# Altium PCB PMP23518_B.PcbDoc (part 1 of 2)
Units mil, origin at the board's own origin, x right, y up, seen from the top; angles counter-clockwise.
Board outline 2200 x 2200 mil, 2 copper layers (Top Layer, Bottom Layer), stack 62 mil thick; 74 components, 34 nets, 163 pads, 51 vias.
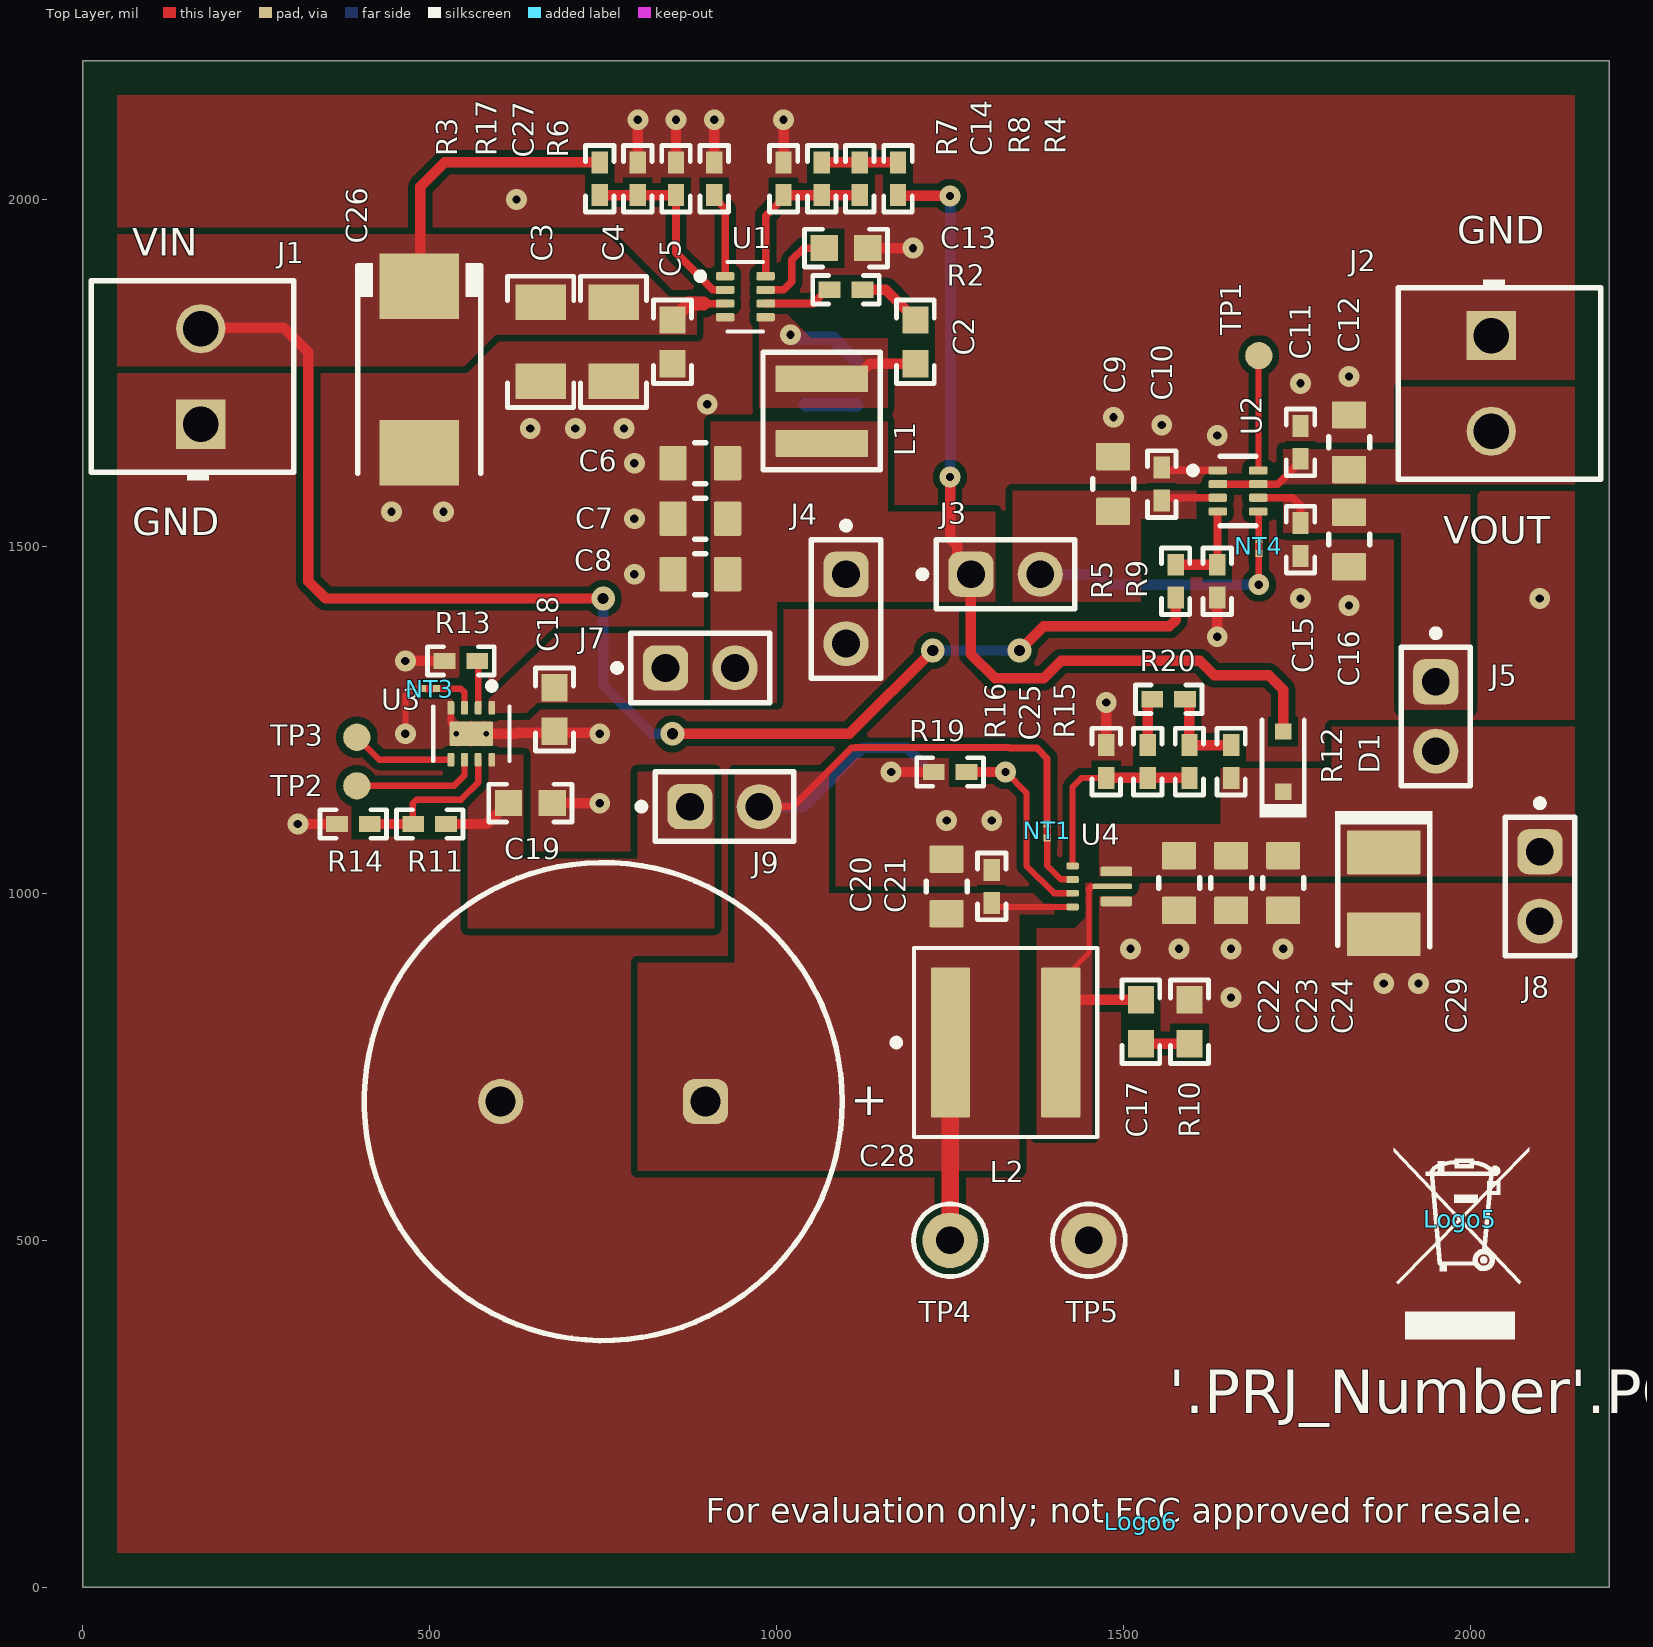
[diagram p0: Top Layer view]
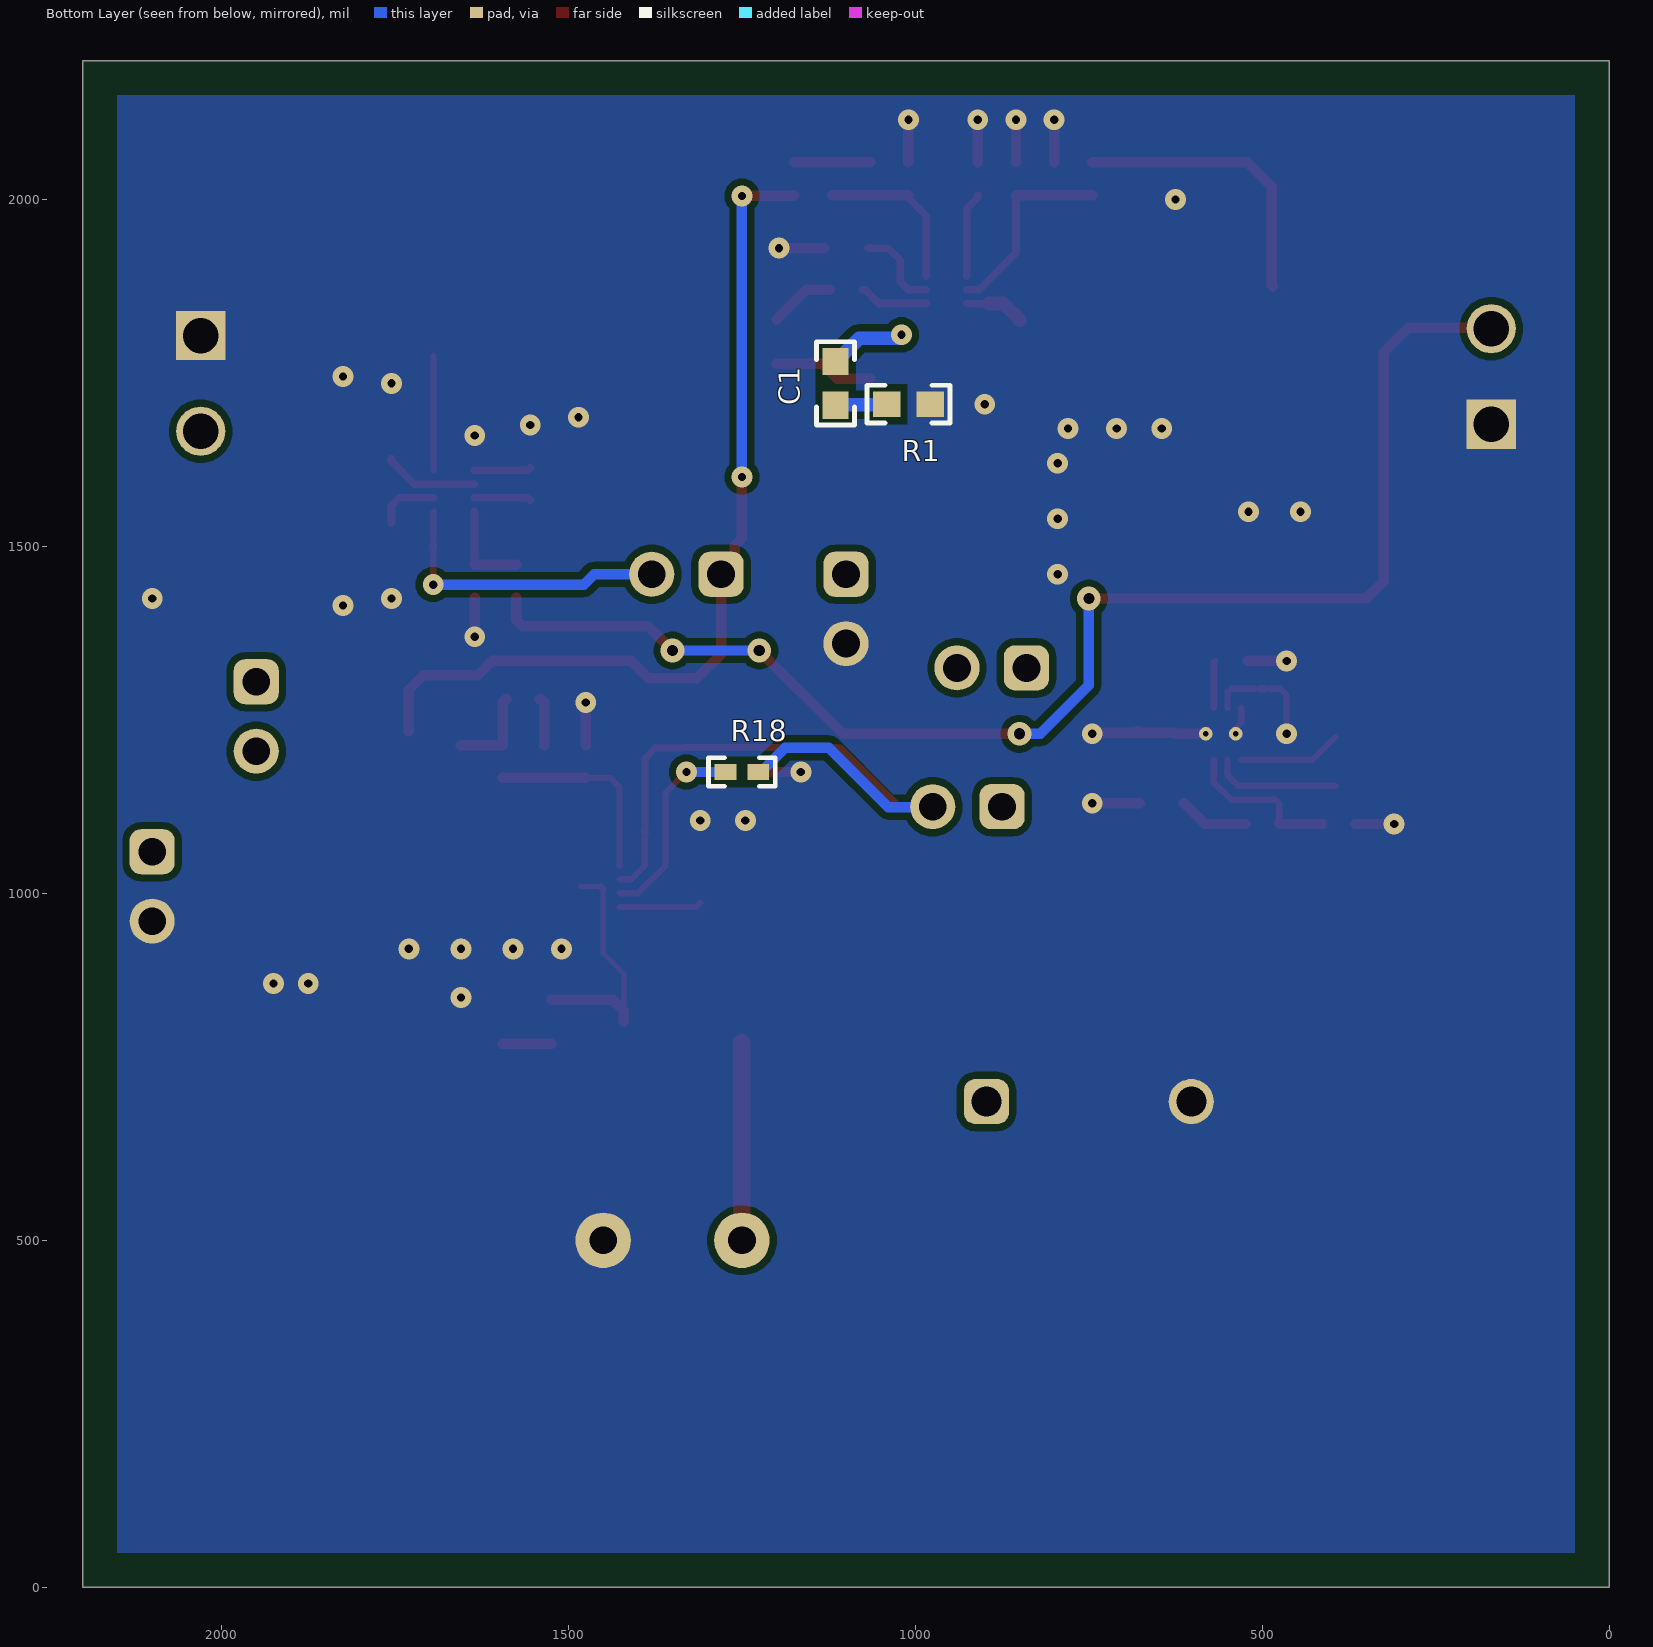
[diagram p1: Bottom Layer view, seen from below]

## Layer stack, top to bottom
Top Solder: solder mask 0.4, Solder Resist, Dk 3.5
Top Layer: signal copper 1.4
Dielectric1: core 59.2, FR-4 High Tg, Dk 4.8
Bottom Layer: signal copper 1.4
Bottom Solder: solder mask 0.4, Solder Resist, Dk 3.5

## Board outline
0,0 0,2200 2200,2200 2200,0

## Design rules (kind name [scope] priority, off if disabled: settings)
AcuteAngle [All] p1: minimum=4.50000000000000E+0001 checktracksonly=FALSE
AssemblyTestPointUsage [All] p1: valid=2
BoardOutlineClearance BoardOutlineClearance_MountingHoles [OnCopper and InComponentClass('Mounting Holes')] p1: gap=39.37 ignorepadtopadclearanceinfootprint=FALSE
BoardOutlineClearance BoardOutlineClearance_Poly [OnCopper and IsPoly] p2: gap=25 ignorepadtopadclearanceinfootprint=FALSE
BoardOutlineClearance [OnCopper and Not InComponentClass('Logo') and not InComponentClass('FiducialMark') and not InRegion(1000,500,4000,800) and not InPoly] p3: gap=40 ignorepadtopadclearanceinfootprint=FALSE
Clearance Clearance_Keepouts [((IsTrack Or IsArc) And Not InPoly) And IsFree and IsKeepOut vs ((IsTrack Or IsArc) And Not InPoly) And IsFree and IsKeepOut] p1: gap=0 ignorepadtopadclearanceinfootprint=FALSE
Clearance Clearance_Poly [InPolygon] p2: gap=10 ignorepadtopadclearanceinfootprint=TRUE
Clearance Clearance_FiducialMark [IsKeepOut and InComponentClass('FiducialMark') vs IsPad and InComponentClass('FiducialMark')] p3: gap=0 ignorepadtopadclearanceinfootprint=FALSE
Clearance [All] p4: gap=7.87 ignorepadtopadclearanceinfootprint=TRUE
ComponentClearance ComponentClearance_MountingHoles_FiducialMarks [InComponentClass('Mounting Holes') vs InComponentClass('FiducialMark')] p1: gap=50 collisioncheckmode=3 verticalgap=10 showdistances=FALSE
ComponentClearance ComponentClearance_Shunt [InComponentClass('Header') vs InComponentClass('Shunt')] p2: gap=0 collisioncheckmode=3 verticalgap=0 showdistances=FALSE
ComponentClearance ComponentClearance_Logo [InComponentClass('Logo')] p3: gap=30 collisioncheckmode=3 verticalgap=10 showdistances=FALSE
ComponentClearance ComponentClearance_ScrewToNut [(HasFootprint('NY PMS 440 0025 PH')) vs (HasFootprint('Keystone_1902C'))] p4: gap=5 collisioncheckmode=3 verticalgap=10 showdistances=FALSE
ComponentClearance ComponentClearance_MountingHoles [InComponentClass('Mounting Holes')] p5: gap=100 collisioncheckmode=3 verticalgap=100000 showdistances=FALSE
ComponentClearance ComponentClearance_SmallPassives [HasFootprint('0201*') or HasFootprint('0402*') or HasFootprint('0508') or HasFootprint('0603*') or HasFootprint('0612') or HasFootprint('0805*') or HasFootprint('0815*') or HasFootprint('0830*') or HasFootprint('1206*') or HasFootprint('1210*') or HasFootprint('1808*') or HasFootprint('1812*') or HasFootprint('1825*') or HasFootprint('2010*') or HasFootprint('2220*') or HasFootprint('2225*') or HasFootprint('2512*') or HasFootprint('2728*') or HasFootprint('3518*') vs HasFootprint('0201*') or HasFootprint('0402*') or HasFootprint('0508') or HasFootprint('0603*') or HasFootprint('0612') or HasFootprint('0805*') or HasFootprint('0815*') or HasFootprint('0830*') or HasFootprint('1206*') or HasFootprint('1210*') or HasFootprint('1808*') or HasFootprint('1812*') or HasFootprint('1825*') or HasFootprint('2010*') or HasFootprint('2220*') or HasFootprint('2225*') or HasFootprint('2512*') or HasFootprint('2728*') or HasFootprint('3518*')] p6: gap=14.96 collisioncheckmode=3 verticalgap=10 showdistances=FALSE
ComponentClearance ComponentClearance_THtoSMT [IsThruComponent vs IsSMTComponent] p7: gap=30 collisioncheckmode=3 verticalgap=30 showdistances=FALSE
ComponentClearance ComponentClearance_THtoTH [IsThruComponent vs IsThruComponent] p8: gap=20 collisioncheckmode=3 verticalgap=30 showdistances=FALSE
ComponentClearance [All] p9: gap=20 collisioncheckmode=3 verticalgap=10 showdistances=FALSE
DiffPairsRouting [All] p1: maxlimit=100 minlimit=10 mostfreqgap=10 toplayer_minwidth=15 toplayer_maxwidth=15 toplayer_prefwidth=15 bottomlayer_minwidth=15 bottomlayer_maxwidth=15 bottomlayer_prefwidth=15 maxuncoupledlength=1000
FabricationTestPointUsage TestPointUsage [All] p1: valid=2 allowmultiple=FALSE
FabricationTestpoint Testpoint [All] p1: side=3 testpointundercomponent=TRUE minsize=40 maxsize=100 preferedsize=60 minholesize=0 maxholesize=40 preferedholesize=32 testpointgrid=1 allowsidetop=TRUE allowsidebottom=TRUE usegrid=TRUE gridtolerance=0.01
FanoutControl Fanout_LCC [IsLCC] p1: bgadir=Out bgaviamode=Centered fanoutstyle=Auto fanoutdirection=Alternating viagrid=1 // Fanout_LCC (Default Rule)
FanoutControl Fanout_BGA [IsBGA] p2: bgadir=Out bgaviamode=Centered fanoutstyle=Auto fanoutdirection=Alternating viagrid=1 // Fanout_BGA (Default Rule)
FanoutControl Fanout_Default [All] p4: bgadir=Out bgaviamode=Centered fanoutstyle=Auto fanoutdirection=Alternating viagrid=1 // Fanout_Default (Default Rule)
FanoutControl Fanout_Small [(CompPinCount < 5)] p5: bgadir=Out bgaviamode=Centered fanoutstyle=Auto fanoutdirection=OutThenIn viagrid=1 // Fanout_Small (Default Rule)
HoleSize [All] p1: absolutevalues=TRUE maxlimit=251 minlimit=7.87 maxpercent=80.000 minpercent=20.000
MinimumAnnularRing MinimumAnnularRing_ThermalPadVias [IsVia and InAnyComponent] p1: minimumring=5.91
MinimumAnnularRing [All] p2: minimumring=7.87
MinimumSolderMaskSliver MinimumSolderMaskSliver_Logo [InComponentClass('Logo') vs InComponentClass('Logo')] p1: minsoldermaskwidth=0.7
MinimumSolderMaskSliver [All] p2: minsoldermaskwidth=3.94
PlaneConnect [All] p1: planeconnectstyle=Relief reliefexpansion=10 reliefentries=4 reliefconductorwidth=10 reliefairgap=10
PolygonConnect [All] p1: connectstyle=Direct reliefconductorwidth=10 reliefentries=4 polygonreliefangle="90 Angle" airgapwidth=10
RoutingVias ThermalPadVias [IsVia and InAnyComponent] p1: holewidth=7.87 width=19.68 viastyle="Through Hole" minholewidth=7.87 minwidth=19.68 maxholewidth=12.99 maxwidth=23.62
RoutingVias [All] p2: holewidth=16 width=34 viastyle="Through Hole" minholewidth=7.87 minwidth=24 maxholewidth=40 maxwidth=65
SilkToBoardRegionClearance [Not ((IsComment or IsDesignator) And (Hide <> 'False')) and not InRegion(1000,500,4000,800)] p1:
SilkToSilkClearance SilkToSilkClearance_Pb-FreeLogo [(HasFootprint('Pb-Free_Overlay_Medium') OR HasFootprint('Pb-Free_Overlay_Small')) vs (HasFootprint('Pb-Free_Overlay_Medium') OR HasFootprint('Pb-Free_Overlay_Small'))] p1: silktosilkclearance=0
SilkToSilkClearance [All] p2: silktosilkclearance=3.94
SilkToSolderMaskClearance SilkToComponentPadClearance [(IsPad or IsFill or IsRegion) and InAnycomponent] p1: minsilkscreentomaskgap=5 clearancetoexposedcopper=TRUE
SilkToSolderMaskClearance "Silk to Solder Mask Opening" [All] p2: minsilkscreentomaskgap=3.94 clearancetoexposedcopper=FALSE
SolderMaskExpansion [All] p1: expansion=1.97 istentingtop=FALSE
UnRoutedNet [All] p1: checkbadconnections=TRUE
Width [All] p1: maxlimit=100 minlimit=6 preferedwidth=10 checkconnectedcopper=TRUE
14 further rules are at their usual default settings.

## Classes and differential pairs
component class Header: J3 J4 J5 J7 J8 J9

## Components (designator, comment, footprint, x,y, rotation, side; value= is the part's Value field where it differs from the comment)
C1 "885012006057" 0603 1115,1735 r90 bottom value=100pF
C2 "885012206071" 0603 1200,1795 r270 top value=0.1uF
C3 "885012208069" 1206 660,1795 r90 top value=10uF
C4 "885012208069" 1206 765,1795 r90 top value=10uF
C5 "885012206071" 0603 850,1795 r90 top value=0.1uF
C6 "GRM21BR61A226ME44L" 0805_HV1 890,1620 r0 top value=22uF
C7 "GRM21BR61A226ME44L" 0805_HV1 890,1540 r0 top value=22uF
C8 "GRM21BR61A226ME44L" 0805_HV1 890,1460 r0 top value=22uF
C9 "GRM21BR61A226ME44L" 0805_HV1 1485,1590 r270 top value=22uF
C10 "885012105010" 0402 1555,1590 r90 top value=0.1uF
C11 "885012105010" 0402 1755,1650 r90 top value=0.1uF
C12 "GRM21BR61A226ME44L" 0805_HV1 1825,1650 r270 top value=22uF
C13 "885012206089" 0603 1100,1930 r180 top value=0.01uF
C14 "885012005055" 0402 1065,2030 r270 top value=10pF
C15 "885012105010" 0402 1755,1510 r270 top value=0.1uF
C16 "GRM21BR61A226ME44L" 0805_HV1 1825,1510 r270 top value=22uF
C17 "885012006057" 0603 1525,815 r90 top value=100pF
C18 "885012206026" 0603 680,1265 r90 top value=1uF
C19 "885012206026" 0603 645,1130 r180 top value=1uF
C20 "GRM21BR61A226ME44L" 0805_HV1 1245,1010 r270 top value=22uF
C21 "885012105010" 0402 1310,1010 r90 top value=0.1uF
C22 "GRM21BR61A226ME44L" 0805_HV1 1580,1015 r90 top value=22uF
C23 "GRM21BR61A226ME44L" 0805_HV1 1655,1015 r90 top value=22uF
C24 "GRM21BR61A226ME44L" 0805_HV1 1730,1015 r90 top value=22uF
C25 "GRM1555C1H181JA01D" 0402 1535,1190 r270 top value=180pF
C26 "20TQC100MYF" Panasonic_D3L 485,1755 r270 top value=100uF
C27 "885012005061" 0402 855,2030 r270 top value=100pF
C28 "850617022001" WCAP-STSC_D16H25 750,700 r0 top
C29 "6TPE100MAZB" 3528-20 1875,1000 r270 top value=100uF
D1 "BAT54WS-7-F" SOD-323 1730,1190 r90 top value=30V
J1 "691214110002" Wurth_691214110002 170,1745 r90 top
J2 "691214110002" Wurth_691214110002 2030,1735 r270 top
J3 "TSW-102-07-G-S" TSW-102-07-G-S 1330,1460 r0 top
J4 "TSW-102-07-G-S" TSW-102-07-G-S 1100,1410 r270 top
J5 "TSW-102-07-G-S" TSW-102-07-G-S 1950,1255 r270 top
J7 "TSW-102-07-G-S" TSW-102-07-G-S 890,1325 r0 top
J8 "TSW-102-07-G-S" TSW-102-07-G-S 2100,1010 r270 top
J9 "TSW-102-07-G-S" TSW-102-07-G-S 925,1125 r0 top
L1 "XGL4020-682MEC" FP-XGL4020-682MEC_SMD2-MFG 1065,1695 r270 top
L2 "XGL6030-102MEC" FP-XGL6030-102MEC_SMT2_6MM51_6MM71-MFG 1330,785 r0 top value=1uH
Logo5 "WEEE logo" WEEE_Minimum 1985,530 r0 top
Logo6 "FCC disclaimer" FCC_disclaimer 1524.81,95 r0 top
NT1 "Net-Tie" Net-Tie_10mil 1390,1090 r270 top net-tie
NT3 "Net-Tie" Net-Tie_10mil 500,1295 r0 top net-tie
NT4 "Net-Tie" Net-Tie_10mil 1695,1500 r270 top net-tie
R1 "CRCW060310R0JNEA" 0603 1010,1705 r180 bottom value=10
R2 "CRCW04022R20JNED" 0402 1100,1870 r0 top value=2.2
R3 "CRCW0402154KFKED" 0402 745,2030 r270 top value=154k
R4 "CRCW04020000Z0ED" 0402 1175,2030 r270 top value=0
R5 "CRCW040280K6FKED" 0402 1575,1450 r90 top value=80.6k
R6 "CRCW040220K5FKED" 0402 910,2030 r90 top value=20.5k
R7 "CRCW040210K0FKED" 0402 1010,2030 r90 top value=10.0k
R8 "CRCW040235K7FKED" 0402 1120,2030 r270 top value=35.7k
R9 "CRCW040210K0FKED" 0402 1635,1450 r270 top value=10.0k
R10 "CRCW060310R0JNEA" 0603 1595,815 r90 top value=10
R11 "CRCW0402301KFKED" 0402 500,1100 r180 top value=301k
R12 "CRCW04020000Z0ED" 0402 1655,1190 r270 top value=0
R13 "CRCW0402374RFKED" 0402 545,1335 r180 top value=374
R14 "CRCW0402200KFKED" 0402 390,1100 r180 top value=200k
R15 "CRCW0402511KFKED" 0402 1595,1190 r270 top value=511k
R16 "CRCW0402100KFKED" 0402 1475,1190 r90 top value=100k
R17 "CRCW040224K9FKED" 0402 800,2030 r90 top value=24.9k
R18 "CRCW04020000Z0ED" 0402 1250,1175 r0 bottom value=0
R19 "CRCW04020000Z0ED" 0402 1250,1175 r0 top value=0
R20 "CRCW04022K00FKED" 0402 1565,1280 r0 top value=2.00k
TP1 "TP_SM_1MM" TP_SM_1MM 1695,1775 r0 top
TP2 "TP_SM_1MM" TP_SM_1MM 395,1155 r0 top
TP3 "TP_SM_1MM" TP_SM_1MM 395,1225 r0 top
TP4 "5002" Keystone5002 1250,500 r90 top
TP5 "5001" Keystone5001 1450,500 r90 top
U1 "TPS62932DRLR" DRL0008A-MFG 955,1860 r0 top
U2 "TPS2116DRLR" DRL0008A-MFG 1665,1580 r0 top
U3 "BQ25173DSG" DSG0008A-MFG 560,1230 r270 top
U4 "TPS61022RWUR" RWU0007A 1465,1010 r180 top

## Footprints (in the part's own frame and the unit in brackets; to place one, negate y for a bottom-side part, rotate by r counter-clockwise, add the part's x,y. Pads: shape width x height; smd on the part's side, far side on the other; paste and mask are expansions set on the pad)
0402 [mm] "0402 from SM-752 data"
  rect 0.8x0.6 smd: 1(-0.6,0) 2(0.6,0)
  silkscreen extent -1.22,-0.52 1.22,0.52, body extent -0.55,-0.3 0.55,0.3, height 0.6
0603 [mm] "0603 from SM-752 data"
  rect 1x0.95 smd: 1(-0.8,0) 2(0.8,0)
  silkscreen extent -1.52,-0.69 1.52,0.69, body extent -0.87,-0.47 0.87,0.47, height 1
0805_HV1 [mm] "Custom footprint based on analyzing multiple manufacturer recommendations"
  rrect10% 1x1.25 smd: 1(-1,0) 2(1,0)
  silkscreen extent -0.2,-0.75 0.2,0.75, body extent -1.1,-0.72 1.1,0.73, height 1.45
1206 [mm] "1206 from SM-752 data"
  rect 1.3x1.85 smd: 1(-1.45,0) 2(1.45,0)
  silkscreen extent -2.4,-1.21 2.4,1.21, body extent -1.7,-0.9 1.7,0.9, height 1.35
3528-20 [mm] "SMD, 2-Leads, Body 3.5x2.8mm"
  rrect6% 1.6x2.7 smd: 1(-1.5,0) 2(1.5,0)
  silkscreen extent -3.02,-1.79 1.95,1.79, body extent -1.85,-1.5 1.85,1.5, height 2.01
DRL0008A-MFG [mm]
  rrect33% 0.67x0.3 smd paste+0 mask+0: 1(-0.74,0.75) 2(-0.74,0.25) 3(-0.74,-0.25) 4(-0.74,-0.75) 5(0.74,-0.75) 6(0.74,-0.25) 7(0.74,0.25) 8(0.74,0.75)
  silkscreen extent -1.77,-1.28 0.65,1.28, body extent -1.17,-1.35 1.17,1.35, height 0.25
DSG0008A-MFG [mm]
  rrect40% 0.5x0.25 smd paste+0 mask+0: 1(-0.95,0.75) 2(-0.95,0.25) 3(-0.95,-0.25) 4(-0.95,-0.75) 5(0.95,-0.75) 6(0.95,-0.25) 7(0.95,0.25) 8(0.95,0.75)
  rrect11% 0.9x1.6 smd paste-1000 mask+0: 9(0,0)
  silkscreen extent -1.87,-1.39 1,1.4, body extent -1.3,-1.15 1.3,1.15, height 0.25
FCC_disclaimer [mil]
FP-XGL4020-682MEC_SMD2-MFG [mm]
  rrect10% 0.98x3.4 smd paste+0 mask+0: 1(-1.185,0) 2(1.185,0)
  silkscreen extent -2.15,-2.15 2.15,2.15, body extent -2.25,-2.25 2.25,2.25, height 0.25
FP-XGL6030-102MEC_SMT2_6MM51_6MM71-MFG [mm]
  rrect7% 1.43x5.5 smd paste+0 mask+0: 1(-2.02,0) 2(2.02,0)
  silkscreen extent -4.12,-3.45 3.35,3.45, body extent -3.45,-3.55 3.45,3.55, height 0.25
Keystone5001 [mil] "For Keystone 500x miniature loop terminals"
  round 80 hole 40: 1(0,0)
  silkscreen extent -52,-52 52,52, body extent -49,-49 49,49, height 182
Keystone5002 [mil] "For Keystone 500x miniature loop terminals"
  round 80 hole 40: 1(0,0)
  silkscreen extent -52,-52 52,52, body extent -49,-49 49,49, height 182
Net-Tie_10mil [mil] "10mil net tie, no solder mask opening, no solder paste"
  rect 10x10 smd paste-5 mask-5: 1(-10,0) 2(10,0)
  Top Layer region: -6,5 6,5 6,-5 -6,-5
Panasonic_D3L [mm] "SMD, 2-Leads, Body 7.3x4.3mm"
  rect 2.4x2.9 smd: 1(-3.05,0) 2(3.05,0)
  silkscreen extent -3.9,-2.25 3.8,2.25, body extent -3.8,-2.25 3.8,2.25, height 3.01
RWU0007A [mm] "VQFN-HR-7"
  rrect29% 1.15x0.35 smd paste-0.5: 1(-0.625,0.55) 3(-0.625,-0.55)
  rrect50% 1.45x0.2 smd paste-0.5: 2(-0.475,0)
  rrect40% 0.45x0.25 smd: 4(0.975,-0.75) 5(0.975,-0.25) 6(0.975,0.25) 7(0.975,0.75)
  body extent -1,-1 1,1, height 1
SOD-323 [mm] "NXP recommended land pattern"
  rect 0.6x0.6 smd paste-0.05: 1(-1.1,0) 2(1.1,0)
  silkscreen extent -2.06,-0.86 1.53,0.86, body extent -1.3,-0.67 1.3,0.68, height 1.1
TP_SM_1MM [mm] "1mm Test Point, SMT"
  round 1 smd paste-0.5: 1(0,0)
TSW-102-07-G-S [mm] "Samtec 100mil, 1x2, 230 mil above insulator"
  rrect50% 1.65x1.65 hole 1.016: 1(-1.27,0)
  round 1.65 hole 1.016: 2(1.27,0)
  silkscreen extent -3.17,-1.27 2.54,1.27, body extent -2.54,-1.27 2.54,1.27, height 8.38
WCAP-STSC_D16H25 [mm] "Supercapacitors, THT, body diameter 16mm"
  rrect50% 1.65x1.65 hole 1.1: 1(3.75,0)
  round 1.65 hole 1.1: 2(-3.75,0)
  silkscreen extent -8.75,-8.75 8.75,8.75, body extent -7.99,-8 8,8, height 25.09
WEEE_Minimum [mil] "WEEElie bin"
  silkscreen extent -95,-172 99,104
Wurth_691214110002 [mm] "Receptacle, 3.5mm, 2x1, TH"
  rect 1.8x1.8 hole 1.3: 1(-1.75,0)
  round 1.8 hole 1.3: 2(1.75,0)
  silkscreen extent -3.8,-3.4 3.5,4, body extent -3.9,-3.4 3.5,4, height 8.5

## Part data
C1 C17: library part CMP-0006822-4, "CAP, CERM, 100 pF, 50 V, +/- 5%, C0G/NP0, 0603", Cap_Case=0603, Manufacturer="Wurth Elektronik", TempCo=C0G/NP0, Tolerance_%=5%, Value1=Unknown, Value2=50V, ValueDisplayed=100pF
C2 C5: library part CMP-0006832-5, "CAP, CERM, 0.1 uF, 25 V, +/- 10%, X7R, 0603", Cap_Case=0603, Manufacturer="Wurth Elektronik", Supplier Part Number 1=710-885012206071, TempCo=X7R, Tolerance_%=10%, Value1=Unknown, Value2=25V, ValueDisplayed=0.1uF
C3 C4: library part CMP-0008574-2, "CAP, CERM, 10 uF, 25 V, +/- 10%, X7R, 1206", Cap_Case=1206, Manufacturer="Wurth Elektronik", Supplier Part Number 1=732-7574-1-ND, TempCo=X7R, Tolerance_%=10%, Value1=Unknown, Value2=25V, ValueDisplayed=10uF
C6 C7 C8 C9 C12 C16 C20 C22 C23 C24: library part CMP-0008286-2, "CAP, CERM, 22 uF, 10 V, +/- 20%, X5R, 0805", Cap_Case=0805, Manufacturer=MuRata, Supplier Part Number 1=490-10746-1-ND, TempCo=X5R, Tolerance_%=20%, Value1=Unknown, Value2=10V, ValueDisplayed=22uF
C10 C11 C15 C21: library part CMP-0006221-2, "CAP, CERM, 0.1 uF, 10 V, +/- 20%, X5R, 0402", Cap_Case=0402, Manufacturer="Wurth Elektronik", Supplier Part Number 1=732-7487-1-ND, TempCo=X5R, Tolerance_%=20%, Value1=Unknown, Value2=10V, ValueDisplayed=0.1uF
C13: library part CMP-0750039-1, "CAP, CERM, 0.01 µF, 50 V,+/- 10%, X7R, 0603", Cap_Case=0603, Manufacturer="Wurth Elektronik", TempCo=X7R, Tolerance_%=10%, Value2=50V, ValueDisplayed=0.01µF
C14: library part CMP-0006215-2, "CAP, CERM, 10 pF, 50 V, +/- 5%, C0G/NP0, 0402", Cap_Case=0402, Manufacturer="Wurth Elektronik", Supplier Part Number 1=732-7469-1-ND, TempCo=C0G/NP0, Tolerance_%=5%, Value1=Unknown, Value2=50V, ValueDisplayed=10pF
C18 C19: library part CMP-0064932-4, "CAP, CERM, 1 uF, 10 V,+/- 10%, X7R, 0603", Cap_Case=0603, Manufacturer="Wurth Elektronik", Supplier Part Number 1=732-7945-1-ND, TempCo=X7R, Tolerance_%=10%, Value1=Unknown, Value2=10V, ValueDisplayed=1uF
C25: library part CMP-0006425-2, "CAP, CERM, 180 pF, 50 V, +/- 5%, C0G/NP0, 0402", Cap_Case=0402, Manufacturer=MuRata, Supplier Part Number 1=490-3231-1-ND, TempCo=C0G/NP0, Tolerance_%=5%, Value1=Unknown, Value2=50V, ValueDisplayed=180pF
C26: library part CMP-0012616-3, "CAP, Tantalum Polymer, 100 uF, 20 V, +/- 20%, 0.055 ohm, 7.3x4.3mm SMD", Cap_Case=7.3x4.3x2.8mm, Manufacturer=Panasonic, Supplier Part Number 1=P16503CT-ND, Tolerance_%=20%, Value1="0.055 ohm", Value2=20V, ValueDisplayed=100uF
C27: library part CMP-0006217-2, "CAP, CERM, 100 pF, 50 V, +/- 5%, C0G/NP0, 0402", Cap_Case=0402, Manufacturer="Wurth Elektronik", Supplier Part Number 1=732-7475-1-ND, TempCo=C0G/NP0, Tolerance_%=5%, Value1=Unknown, Value2=50V, ValueDisplayed=100pF
C28: library part CMP-0102070-1, "WCAP-STSC Supercapacitors (EDLCs), THT, D16 x H25mm, 25F, 2.7VDC", Capacitance Tolerance="-10% / +30%", Discharge Current Max=20.7A, Leakage Current=0.068mA, Manufacturer="Wurth Elektronik", Operating Temperature Max=65°C, Operating Temperature Min=-40°C, Power Density=10.72kW/kg, Rated Discharge Current=6A, Rated Voltage (DC)=2.7V
C29: library part CMP-0077420-3, "CAP, Tantalum Polymer, 100 µF, 6.3 V,+/- 20%, 0.035 ohm, 3528 SMD", Cap_Case=3528-20, Manufacturer=Panasonic, Supplier Part Number 1=P16256CT-ND, Tolerance_%=20%, Value1="0.035 ohm", Value2=6.3V, ValueDisplayed=100µF
D1: library part CMP-0028458-2, "Diode, Schottky, 30 V, 0.2 A, SOD-323", Manufacturer="Diodes Inc.", Value1=0.2A, Value2=0.7V
J1 J2: library part CMP-0054825-2, "Terminal Block, 3.5mm, 2x1, Tin, TH", Color=Green, Current_A=10A, Manufacturer="Wurth Elektronik", Supplier Part Number 1=732-2747-ND, Voltage_V=300V
J3 J4 J5 J7 J8 J9: library part CMP-0075405-3, "Header, 100mil, 2x1, Gold, TH", Color=Black, Current_A=6.3A, Manufacturer=Samtec, Supplier Part Number 1=SAM1029-02-ND, Voltage_V=550V
L1: library part CMP-0087878-1, "Shielded Power Inductors", Manufacturer=Coilcraft
L2: library part CMP-0001586-1, "1 µH Shielded Molded Inductor 18.1 A 4.9mOhm Max Nonstandard", Digikey Part Number=2457-XGL6030-102MEC-ND, Manufacturer=Coilcraft, Operating Temperature Range=to, Self Resonant Frequency=42MHz, Test Frequency=1MHz, Tolerance_%=20%
Logo5: library part CMP-0074769-3, Manufacturer="Texas Instruments"
Logo6: library part CMP-0074847-1, "FCC_disclaimer"
NT1 NT3 NT4: library part CMP-0078142-6, "Single point connection between nets.", Manufacturer=N/A
R1 R10: library part CMP-0025703-4, "RES, 10, 5%, 0.1 W, AEC-Q200 Grade 0, 0603", Manufacturer=Vishay-Dale, Power_W=100mW, Supplier Part Number 1=541-10GCT-ND, TempCo="200 ppm/C", Tolerance_%=5%, Value2=0.1W, Value_Code=10R0, ValueDisplayed=10
R2: library part CMP-0026898-3, "RES, 2.2, 5%, 0.063 W, AEC-Q200 Grade 0, 0402", Manufacturer=Vishay-Dale, Power_W=63mW, Supplier Part Number 1=541-2.2JCT-ND, TempCo="200 ppm/C", Tolerance_%=5%, Value2=0.063W, Value_Code=2R20, ValueDisplayed=2.2
R3: library part CMP-0026023-3, "RES, 154 k, 1%, 0.063 W, AEC-Q200 Grade 0, 0402", Manufacturer=Vishay-Dale, Power_W=63mW, Supplier Part Number 1=541-154KLCT-ND, TempCo="100 ppm/C", Tolerance_%=1%, Value2=0.063W, Value_Code=154k
R4 R12 R18 R19: library part CMP-0026822-3, "RES, 0, 5%, 0.063 W, AEC-Q200 Grade 0, 0402", Manufacturer=Vishay-Dale, Power_W=63mW, Supplier Part Number 1=541-0.0JCT-ND, TempCo="200 ppm/C", Tolerance_%=5%, Value2=0.063W, Value_Code=0000, ValueDisplayed=0
R5: library part CMP-0026570-2, "RES, 80.6 k, 1%, 0.063 W, AEC-Q200 Grade 0, 0402", Manufacturer=Vishay-Dale, Power_W=63mW, Supplier Part Number 1=541-80.6KLCT-ND, TempCo="100 ppm/C", Tolerance_%=1%, Value2=0.063W, Value_Code=80k6, ValueDisplayed=80.6k
R6: library part CMP-0026163-2, "RES, 20.5 k, 1%, 0.063 W, AEC-Q200 Grade 0, 0402", Manufacturer=Vishay-Dale, Power_W=63mW, Supplier Part Number 1=541-20.5KLCT-ND, TempCo="100 ppm/C", Tolerance_%=1%, Value2=0.063W, Value_Code=20k5, ValueDisplayed=20.5k
R7 R9: library part CMP-0025958-3, "RES, 10.0 k, 1%, 0.063 W, AEC-Q200 Grade 0, 0402", Manufacturer=Vishay-Dale, Power_W=63mW, Supplier Part Number 1=541-10.0KLCT-ND, TempCo="100 ppm/C", Tolerance_%=1%, Value2=0.063W, Value_Code=10k0, ValueDisplayed=10.0k
R8: library part CMP-0026310-2, "RES, 35.7 k, 1%, 0.063 W, AEC-Q200 Grade 0, 0402", Manufacturer=Vishay-Dale, Power_W=63mW, Supplier Part Number 1=541-35.7KLCT-ND, TempCo="100 ppm/C", Tolerance_%=1%, Value2=0.063W, Value_Code=35k7, ValueDisplayed=35.7k
R11: library part CMP-0026280-2, "RES, 301 k, 1%, 0.063 W, AEC-Q200 Grade 0, 0402", Manufacturer=Vishay-Dale, Power_W=63mW, Supplier Part Number 1=541-301KLCT-ND, TempCo="100 ppm/C", Tolerance_%=1%, Value2=0.063W, Value_Code=301k
R13: library part CMP-0026318-2, "RES, 374, 1%, 0.063 W, AEC-Q200 Grade 0, 0402", Manufacturer=Vishay-Dale, Power_W=63mW, Supplier Part Number 1=541-374LCT-ND, TempCo="100 ppm/C", Tolerance_%=1%, Value2=0.063W, Value_Code=374R, ValueDisplayed=374
R14: library part CMP-0026158-2, "RES, 200 k, 1%, 0.063 W, AEC-Q200 Grade 0, 0402", Manufacturer=Vishay-Dale, Power_W=63mW, Supplier Part Number 1=541-200KLCT-ND, TempCo="100 ppm/C", Tolerance_%=1%, Value2=0.063W, Value_Code=200k
R15: library part CMP-0026435-2, "RES, 511 k, 1%, 0.063 W, AEC-Q200 Grade 0, 0402", Manufacturer=Vishay-Dale, Power_W=63mW, Supplier Part Number 1=541-511KLCT-ND, TempCo="100 ppm/C", Tolerance_%=1%, Value2=0.063W, Value_Code=511k
R16: library part CMP-0025950-3, "RES, 100 k, 1%, 0.063 W, AEC-Q200 Grade 0, 0402", Manufacturer=Vishay-Dale, Power_W=63mW, Supplier Part Number 1=541-100KLCT-ND, TempCo="100 ppm/C", Tolerance_%=1%, Value2=0.063W, Value_Code=100k
R17: library part CMP-0026196-2, "RES, 24.9 k, 1%, 0.063 W, AEC-Q200 Grade 0, 0402", Manufacturer=Vishay-Dale, Power_W=63mW, Supplier Part Number 1=541-24.9KLCT-ND, TempCo="100 ppm/C", Tolerance_%=1%, Value2=0.063W, Value_Code=24k9, ValueDisplayed=24.9k
R20: library part CMP-0026227-2, "RES, 2.00 k, 1%, 0.063 W, AEC-Q200 Grade 0, 0402", Manufacturer=Vishay-Dale, Power_W=63mW, Supplier Part Number 1=541-2.00KLCT-ND, TempCo="100 ppm/C", Tolerance_%=1%, Value2=0.063W, Value_Code=2k00, ValueDisplayed=2.00k
TP1 TP2 TP3: library part CMP-0003825-1, "1mm Test Point, SMT", Manufacturer=Any
TP4: library part CMP-0055139-2, "Test Point, Miniature, White, TH", Color=White, Manufacturer="Keystone Electronics", Supplier Part Number 1=36-5002-ND
TP5: library part CMP-0055138-2, "Test Point, Miniature, Black, TH", Color=Black, Manufacturer="Keystone Electronics", Supplier Part Number 1=36-5001-ND
U1: library part CMP-0094457-2, "3.8-V to 30-V, 2-A Synchronous Buck Converter in SOT583 Package", Manufacturer="Texas Instruments", Max Supply Voltage=30V, Min Supply Voltage=3.8V, Nominal Supply Current=12uA, Operating Temperature Range="-40°C to +150°C", Output Voltage=0.8-22V, Switching Frequency=310-2100kHz
U2: library part CMP-0088593-2, "1.6 V to 5 V, 2.5-A Low IQ Power Mux With Manual and Automatic Switchover", Manufacturer="Texas Instruments", Max Supply Voltage=5.5V, Min Supply Voltage=1.6V, Nominal Supply Current=0.5-1uA, Operating Temperature Range=to, Output Voltage=0-5.5V
U3: library part CMP-0093602-1, "800-mA Linear Charger for 1- to 4-Cell Super Capacitor", Manufacturer="Texas Instruments", Max Supply Voltage=18V, Min Supply Voltage=3V, Nominal Supply Current=0.35-0.8uA, Operating Temperature Range="-40°C to +125°C", Output Voltage=10.5V
U4: library part CMP-0078852-3, "8-A Boost Converter with 0.5-V Ultra-Low Input Voltage, RWU0007A (VQFN-HR-7)", Alternate Manufacturer="Texas Instruments", Alternate PartNumber=TPS61022RWUT

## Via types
v1: diameter 30, hole 12, Top Layer to Bottom Layer, 45 vias
v2: diameter 34, hole 16, Top Layer to Bottom Layer, 4 vias
v3: diameter 19.68, hole 7.87, Top Layer to Bottom Layer, 2 vias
